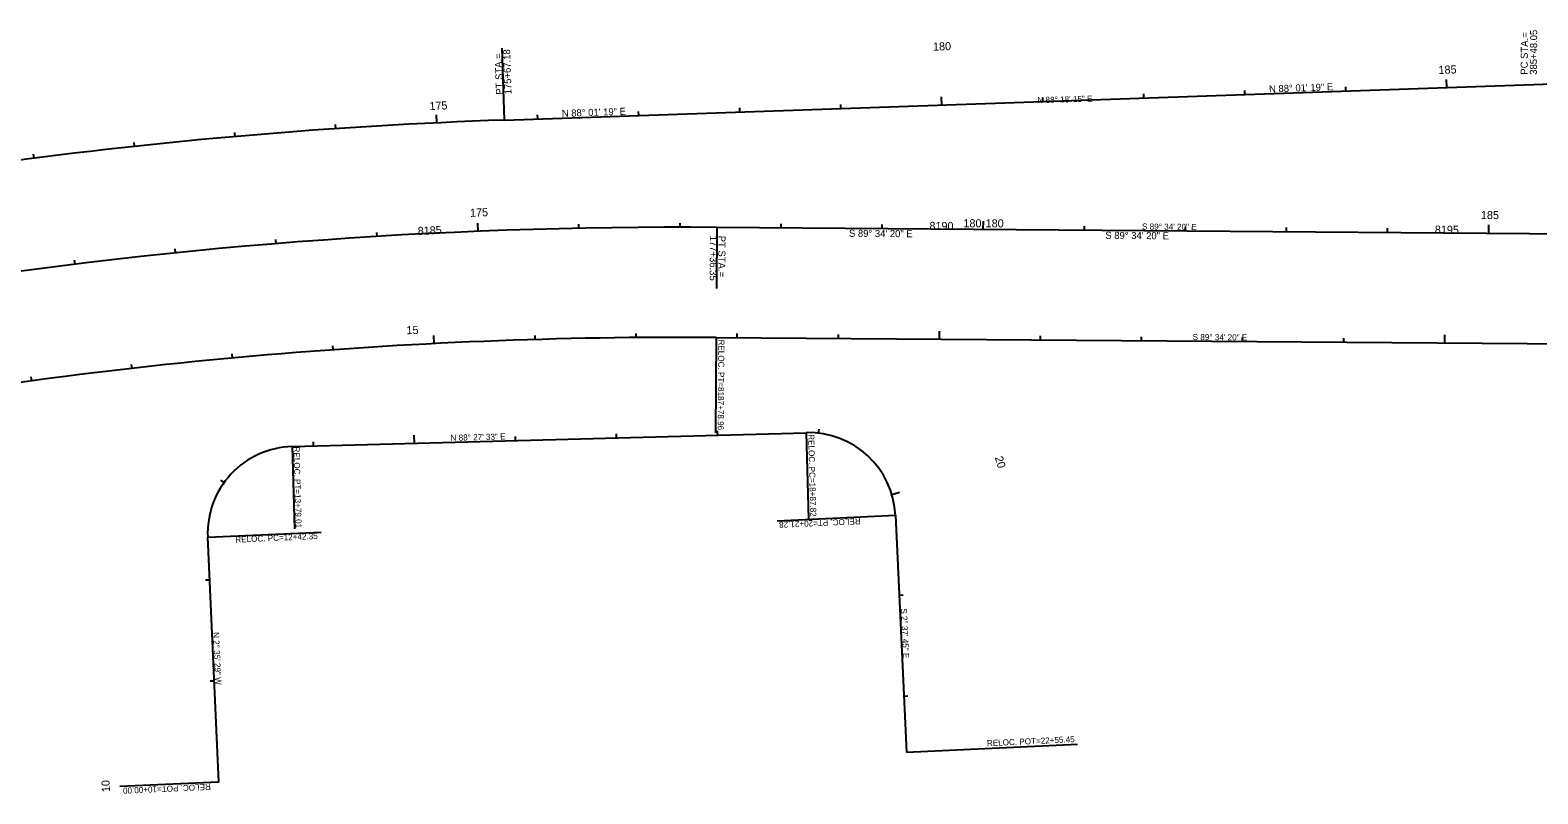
# Model space of a CAD drawing. Extents: x 1944333 to 1978554, y 788952 to 827675.
# Drawn here: x 1968417 to 1969909, y 801753 to 802509 of the extents above; entities that cross this region are included whole.
import ezdxf

# ---------------------------------------------------------------- set-up
doc = ezdxf.new("R2010")
doc.units = 0
for name, color, linetype in [('RD_HC_CL_Rel', 7, 'Continuous'), ('RD_HC_Data_Rel', 7, 'Continuous'), ('RD_HC_Data_Tic_Rel', 7, 'Continuous'), ('RD_HC_TX_Rel_Sta50', 7, 'Continuous')]:
    doc.layers.add(name, color=color, linetype=linetype)

msp = doc.modelspace()

# ---------------------------------------------------------------- linework, layer by layer
at = {"layer": 'RD_HC_CL_Rel'}
for p, q in [((1968886.7, 802419.6), (1970118.4, 802462.2)), ((1969096.7, 802313.5), (1969992.4, 802306.8)), ((1969096.7, 802313.5), (1969992.4, 802306.8)), ((1969095.9, 802204.5), (1970093.4, 802197)), ((1968676.6, 802096.7), (1969185.2, 802110.3)), ((1969273.4, 802028.3), (1969284.2, 801794.4)), ((1968603.9, 801764.7), (1968593, 802006.8))]:
    msp.add_line(p, q, dxfattribs=at)
for centre, radius, start, end in [((1969060, 797402.5), 5020.1, 91.978, 97.7581), ((1969060, 797402.5), 4911.1, 89.5721, 108.942), ((1969060, 797402.5), 4911.1, 89.5721, 108.942), ((1969060, 797402.5), 4802.1, 89.5721, 100.5214), ((1969187.5, 802024.4), 86, 2.6292, 91.5408), ((1968678.9, 802010.7), 86, 91.5408, 182.5913)]:
    msp.add_arc(centre, radius, start, end, dxfattribs=at)
at = {"layer": 'RD_HC_Data_Rel'}
for p, q in [((1968886.7, 802419.6), (1968884.3, 802490.6)), ((1969096.7, 802313.5), (1969096.2, 802252.9)), ((1969095.9, 802204.5), (1969095.2, 802110.1)), ((1969185.2, 802110.3), (1969187.5, 802025)), ((1968676.6, 802096.7), (1968678.8, 802015.3)), ((1969273.4, 802028.3), (1969156.5, 802022.9)), ((1968593, 802006.8), (1968705.1, 802011.9)), ((1969284.2, 801794.4), (1969453.6, 801802.2)), ((1968603.9, 801764.7), (1968506.1, 801760.3))]:
    msp.add_line(p, q, dxfattribs=at)
at = {"layer": 'RD_HC_Data_Tic_Rel'}
for p, q in [((1969619.1, 802444.9), (1969619, 802448.9)), ((1969719, 802448.4), (1969718.9, 802452.4)), ((1969819, 802451.8), (1969818.7, 802459.8)), ((1969119.4, 802427.7), (1969119.3, 802431.7)), ((1969219.3, 802431.1), (1969219.2, 802435.1)), ((1969319.3, 802434.6), (1969319, 802442.6)), ((1969419.2, 802438), (1969419.1, 802442)), ((1969519.2, 802441.5), (1969519, 802445.5)), ((1968819.6, 802416.8), (1968819.2, 802424.8)), ((1968919.5, 802420.7), (1968919.4, 802424.7)), ((1969019.5, 802424.2), (1969019.3, 802428.2)), ((1968620.1, 802403.3), (1968619.7, 802407.3)), ((1968719.8, 802411.1), (1968719.5, 802415.1)), ((1968520.6, 802393.5), (1968520.1, 802397.5)), ((1968421.2, 802381.8), (1968420.7, 802385.8)), ((1968860.4, 802309.5), (1968860.1, 802317.5)), ((1968860.4, 802309.5), (1968860.1, 802317.5)), ((1968960.3, 802312.6), (1968960.2, 802316.6)), ((1968960.3, 802312.6), (1968960.2, 802316.6)), ((1969060.3, 802313.6), (1969060.3, 802317.6)), ((1969060.3, 802313.6), (1969060.3, 802317.6)), ((1969160.3, 802313), (1969160.3, 802317)), ((1969160.3, 802313), (1969160.3, 802317)), ((1969260.3, 802312.2), (1969260.3, 802316.2)), ((1969260.3, 802312.2), (1969260.3, 802316.2)), ((1969360.3, 802311.5), (1969360.4, 802319.5)), ((1969360.3, 802311.5), (1969360.4, 802319.5)), ((1969460.3, 802310.8), (1969460.3, 802314.8)), ((1969460.3, 802310.8), (1969460.3, 802314.8)), ((1969560.3, 802310), (1969560.3, 802314)), ((1969560.3, 802310), (1969560.3, 802314)), ((1969660.3, 802309.3), (1969660.3, 802313.3)), ((1969660.3, 802309.3), (1969660.3, 802313.3)), ((1969760.3, 802308.5), (1969760.3, 802312.5)), ((1969760.3, 802308.5), (1969760.3, 802312.5)), ((1969860.3, 802307.8), (1969860.4, 802315.8)), ((1969860.3, 802307.8), (1969860.4, 802315.8)), ((1968660.8, 802297.4), (1968660.4, 802301.3)), ((1968660.8, 802297.4), (1968660.4, 802301.3)), ((1968760.5, 802304.5), (1968760.3, 802308.5)), ((1968760.5, 802304.5), (1968760.3, 802308.5)), ((1968561.2, 802288.2), (1968560.8, 802292.2)), ((1968561.2, 802288.2), (1968560.8, 802292.2)), ((1968461.8, 802277), (1968461.3, 802281)), ((1968461.8, 802277), (1968461.3, 802281)), ((1969016.9, 802204.4), (1969016.9, 802208.4)), ((1969116.9, 802204.3), (1969116.9, 802208.3)), ((1969216.9, 802203.6), (1969216.9, 802207.6)), ((1969316.9, 802202.8), (1969317, 802210.8)), ((1968717.2, 802192.4), (1968716.9, 802196.3)), ((1968817, 802198.5), (1968816.6, 802206.4)), ((1968916.9, 802202.5), (1968916.8, 802206.5)), ((1969416.9, 802202.1), (1969416.9, 802206.1)), ((1969516.9, 802201.3), (1969516.9, 802205.3)), ((1969616.9, 802200.6), (1969616.9, 802204.6)), ((1969716.9, 802199.8), (1969716.9, 802203.8)), ((1969816.9, 802199.1), (1969816.9, 802207.1)), ((1968518.1, 802173.9), (1968517.6, 802177.9)), ((1968617.5, 802184.2), (1968617.2, 802188.2)), ((1968418.8, 802161.6), (1968418.3, 802165.6)), ((1968797.5, 802099.9), (1968797.3, 802107.9)), ((1968897.5, 802102.6), (1968897.4, 802106.6)), ((1968997.5, 802105.3), (1968997.4, 802109.3)), ((1969097.4, 802108), (1969097.3, 802112)), ((1969197.4, 802109.8), (1969197.8, 802113.8)), ((1968697.6, 802097.2), (1968697.5, 802101.2)), ((1968609.2, 802061), (1968605.9, 802063.4)), ((1969269.9, 802049.2), (1969277.5, 802051.5)), ((1968594.9, 801964.5), (1968590.9, 801964.3)), ((1969277.1, 801949.7), (1969281, 801949.9)), ((1968599.4, 801864.6), (1968595.4, 801864.4)), ((1969281.6, 801849.8), (1969285.6, 801850)), ((1968603.9, 801764.7), (1968596, 801764.3))]:
    msp.add_line(p, q, dxfattribs=at)

# ---------------------------------------------------------------- texts
at = {"layer": 'RD_HC_Data_Rel'}
for s, height, rotation, p in [('PC STA.=', 7, 89.5721, (1969898.9, 802464.5)), ('385+48.05', 7, 89.5721, (1969908, 802464.4)), ('PT STA.=', 7, 91.978, (1968885.2, 802444.9)), ('175+67.18', 7, 91.978, (1968893.6, 802445.2)), ('N 88%%d 01\' 19" E', 7, 1.978, (1969643.1, 802446.9)), ('N 88%%d 01\' 19" E', 7, 1.978, (1968943.4, 802422.7)), ('N 88%%d 18\' 15" E', 6, 1.6958, (1969414, 802436.3)), ('S 89%%d 34\' 20" E', 6, 359.5721, (1969517.3, 802311.3)), ('177+36.35', 7, 269.5721, (1969089.9, 802305.2)), ('PT STA.=', 7, 269.5721, (1969098.3, 802305.2)), ('S 89%%d 34\' 20" E', 7, 359.5721, (1969227.4, 802304.1)), ('S 89%%d 34\' 20" E', 7, 359.5721, (1969481, 802302.1)), ('S 89%%d 34\' 20" E', 6, 359.5721, (1969567.4, 802202)), ('RELOC. PT=8187+78.96', 6, 269.5721, (1969098.2, 802202.5)), ('N 88%%d 27\' 33" E', 6, 1.5408, (1968833.3, 802102.2)), ('RELOC. PC=18+87.82', 6, 271.5408, (1969187, 802108.7)), ('RELOC. PT=13+79.01', 6, 271.5408, (1968677.8, 802096.5)), ('RELOC. PT=20+21.28', 6, 182.6292, (1969238.8, 802025.8)), ('RELOC. PC=12+42.35', 6, 2.5913, (1968620.4, 802001.5)), ('S 2%%d 37\' 45" E', 6, 272.6292, (1969278.7, 801936.4)), ('N 2%%d 35\' 29" W', 6, 272.5913, (1968598.2, 801912.9)), ('RELOC. POT=22+55.45', 6, 2.6292, (1969364, 801800.1)), ('RELOC. POT=10+00.00', 6, 182.5913, (1968595.9, 801763))]:
    msp.add_text(s, height=height, rotation=rotation, dxfattribs=at).set_placement(p)
at = {"layer": 'RD_HC_TX_Rel_Sta50'}
for s, rotation, p in [('180', 1.978, (1969310.7, 802488.2)), ('185', 1.978, (1969810.8, 802465.2)), ('175', 2.7448, (1968812.5, 802429.4)), ('175', 2.3296, (1968852.6, 802323.8)), ('185', 359.5721, (1969852.6, 802321.7)), ('8185', 2.9005, (1968800.9, 802305.8)), ('8190', 359.5721, (1969307, 802310.9)), ('180', 359.5721, (1969340.6, 802313.6)), ('180', 359.5721, (1969362.6, 802313.5)), ('8195', 359.5721, (1969807, 802307.2)), ('15', 1.5408, (1968789.7, 802207.7)), ('20', 286.8057, (1969371.6, 802085.8)), ('10', 92.5913, (1968496.3, 801754.9))]:
    msp.add_text(s, height=8, rotation=rotation, dxfattribs=at).set_placement(p)

doc.saveas('drawing.dxf')
